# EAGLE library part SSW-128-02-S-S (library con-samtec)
THROUGH-HOLE .025" SQ POST SOCKET Source: Samtec SSW.pdf
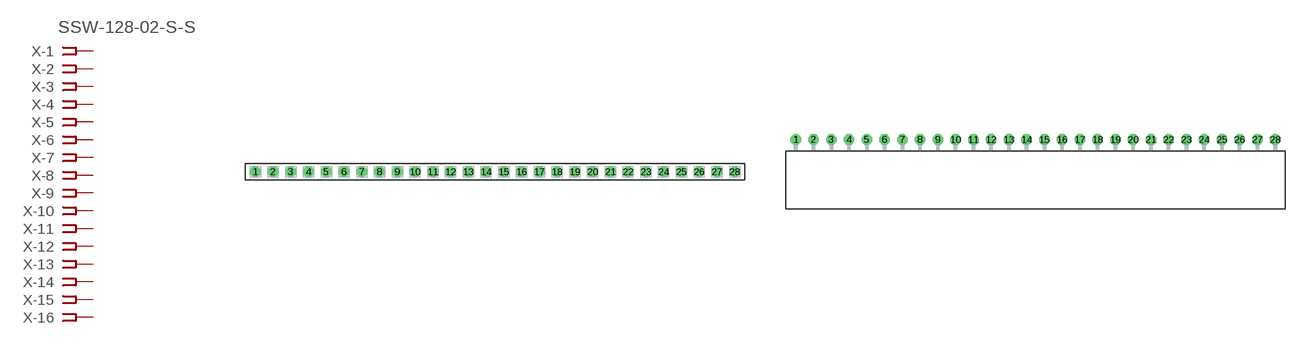
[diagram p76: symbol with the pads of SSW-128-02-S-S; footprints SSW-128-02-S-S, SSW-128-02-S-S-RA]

Designator prefix X; gates -1=FPINV -2=FPIN -3=FPIN -4=FPIN -5=FPIN -6=FPIN -7=FPIN -8=FPIN -9=FPIN -10=FPIN -11=FPIN -12=FPIN -13=FPIN -14=FPIN -15=FPIN -16=FPIN -17=FPIN -18=FPIN -19=FPIN -20=FPIN -21=FPIN -22=FPIN -23=FPIN -24=FPIN -25=FPIN -26=FPIN -27=FPIN -28=FPIN

## SSW-128-02-S-S (MPN: SSW-128-02-S-S; OC_FARNELL: unknown; OC_NEWARK: 11P9775)  [SSW-128-02-S-S]
1  -1:1  pas
2  -2:1  pas
3  -3:1  pas
4  -4:1  pas
5  -5:1  pas
6  -6:1  pas
7  -7:1  pas
8  -8:1  pas
9  -9:1  pas
10  -10:1  pas
11  -11:1  pas
12  -12:1  pas
13  -13:1  pas
14  -14:1  pas
15  -15:1  pas
16  -16:1  pas
17  -17:1  pas
18  -18:1  pas
19  -19:1  pas
20  -20:1  pas
21  -21:1  pas
22  -22:1  pas
23  -23:1  pas
24  -24:1  pas
25  -25:1  pas
26  -26:1  pas
27  -27:1  pas
28  -28:1  pas

## SSW-128-02-S-S-RA (MPN: SSW-128-02-S-S-RA; OC_FARNELL: unknown; OC_NEWARK: 11P9776)  [SSW-128-02-S-S-RA]
Pads as for SSW-128-02-S-S

## Footprint SSW-128-02-S-S (pad centres in mm)
THROUGH-HOLE .025" SQ POST SOCKET Source: Samtec SSW.pdf
drill 1 pad 1.5 octagon: 1 -34.29,0; 2 -31.75,0; 3 -29.21,0; 4 -26.67,0; 5 -24.13,0; 6 -21.59,0; 7 -19.05,0; 8 -16.51,0; 9 -13.97,0; 10 -11.43,0; 11 -8.89,0; 12 -6.35,0; 13 -3.81,0; 14 -1.27,0; 15 1.27,0; 16 3.81,0; 17 6.35,0; 18 8.89,0; 19 11.43,0; 20 13.97,0; 21 16.51,0; 22 19.05,0; 23 21.59,0; 24 24.13,0; 25 26.67,0; 26 29.21,0; 27 31.75,0; 28 34.29,0

## Footprint SSW-128-02-S-S-RA (pad centres in mm)
THROUGH-HOLE .025" SQ POST SOCKET Source: Samtec SSW.pdf
drill 1 pad 1.5 octagon: 1 -34.29,1.524; 2 -31.75,1.524; 3 -29.21,1.524; 4 -26.67,1.524; 5 -24.13,1.524; 6 -21.59,1.524; 7 -19.05,1.524; 8 -16.51,1.524; 9 -13.97,1.524; 10 -11.43,1.524; 11 -8.89,1.524; 12 -6.35,1.524; 13 -3.81,1.524; 14 -1.27,1.524; 15 1.27,1.524; 16 3.81,1.524; 17 6.35,1.524; 18 8.89,1.524; 19 11.43,1.524; 20 13.97,1.524; 21 16.51,1.524; 22 19.05,1.524; 23 21.59,1.524; 24 24.13,1.524; 25 26.67,1.524; 26 29.21,1.524; 27 31.75,1.524; 28 34.29,1.524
